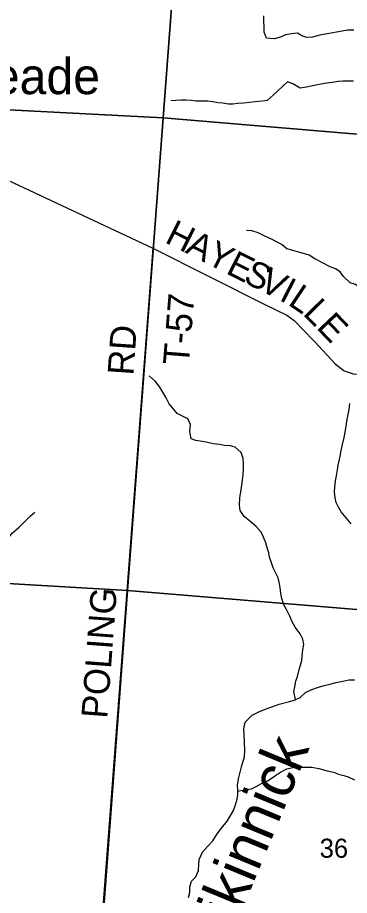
# Model space of a CAD drawing. Extents: x 0 to 42.5, y 0 to 22.
# Drawn here: x 4.623 to 4.986, y 16.014 to 16.976 of the extents above; entities that cross this region are included whole.
import ezdxf

# ---------------------------------------------------------------- set-up
doc = ezdxf.new("R2010")
doc.units = 0
for name, color, linetype in [('GM_X_County_Road', 7, 'Continuous'), ('GM_X_County_Road_Text', 7, 'Continuous'), ('GM_X_Minor_River', 7, 'Continuous'), ('GM_X_Minor_River_Text', 7, 'Continuous'), ('GM_X_Section', 7, 'Continuous'), ('GM_X_Section_Text', 7, 'Continuous'), ('GM_X_Township_Road', 7, 'Continuous'), ('GM_X_Township_Road_Text', 7, 'Continuous'), ('GM_X_Unincorporated_Text', 7, 'Continuous')]:
    doc.layers.add(name, color=color, linetype=linetype)

msp = doc.modelspace()

# ---------------------------------------------------------------- linework, layer by layer
at = {"layer": 'GM_X_County_Road'}
for points in [[(4.39163, 16.96049), (4.41637, 16.94481), (4.50621, 16.88786), (4.51318, 16.88268), (4.52161, 16.86914), (4.54011, 16.83463), (4.58198, 16.81209), (4.77079, 16.72352), (4.89442, 16.66131), (4.91761, 16.6499), (4.9257, 16.64432), (4.94699, 16.62222)], [(4.94699, 16.62222), (4.94734, 16.62187), (4.94838, 16.62078), (4.97069, 16.59667), (4.98046, 16.58918), (4.99047, 16.58587), (5.03773, 16.58279)]]:
    msp.add_lwpolyline(points, dxfattribs=at)
at = {"layer": 'GM_X_Minor_River'}
for points in [[(4.991, 16.96236), (4.98412, 16.9626), (4.97818, 16.9615), (4.97225, 16.96021), (4.96422, 16.95894), (4.95388, 16.95693), (4.94566, 16.9549), (4.93953, 16.95437), (4.93399, 16.95612), (4.92922, 16.95901), (4.9229, 16.95848), (4.9164, 16.95739), (4.91085, 16.95496), (4.90377, 16.95312), (4.89554, 16.95355), (4.89269, 16.96022), (4.8927, 16.96611), (4.89233, 16.97257), (4.89253, 16.97808)], [(4.99088, 16.9067), (4.98572, 16.90674), (4.97902, 16.9066), (4.97386, 16.90607), (4.96735, 16.90517), (4.95893, 16.9039), (4.94745, 16.90189), (4.93923, 16.90005), (4.93234, 16.89877), (4.92412, 16.90358), (4.91858, 16.90571), (4.90287, 16.8912), (4.89597, 16.88536), (4.89061, 16.88483), (4.88315, 16.88394), (4.87684, 16.88322), (4.87014, 16.88232), (4.86402, 16.88198), (4.85866, 16.88145), (4.85388, 16.8813), (4.84757, 16.88229), (4.8426, 16.8829), (4.8361, 16.88409), (4.83113, 16.8845), (4.82424, 16.88455), (4.81812, 16.88479), (4.81334, 16.8852), (4.80722, 16.88563), (4.80206, 16.88585), (4.79613, 16.88552), (4.79096, 16.88518)], [(4.87366, 16.74325), (4.87883, 16.74284), (4.8859, 16.74051), (4.89163, 16.73781), (4.90195, 16.73317), (4.90672, 16.73029), (4.91246, 16.7274), (4.91811, 16.72275)], [(5.00965, 16.61254), (5.02155, 16.63197), (5.02497, 16.63726), (5.02897, 16.64389), (5.02955, 16.64863), (5.02729, 16.65585), (5.02427, 16.66061), (5.02011, 16.66557), (5.01083, 16.6715), (5.00572, 16.67418), (4.99834, 16.67953), (4.99303, 16.68373), (4.98716, 16.68566), (4.97978, 16.69234), (4.976, 16.69748), (4.97089, 16.70092), (4.96502, 16.70323), (4.94835, 16.71166), (4.9421, 16.71568), (4.91811, 16.72275)], [(4.92712, 16.22869), (4.92542, 16.23766), (4.92638, 16.24259), (4.92772, 16.24885), (4.92944, 16.25396), (4.93135, 16.26155), (4.93269, 16.26628), (4.93403, 16.2714), (4.93461, 16.27633), (4.93539, 16.28335), (4.93616, 16.28923), (4.93522, 16.29493), (4.93239, 16.30064), (4.92691, 16.30807), (4.92332, 16.31454), (4.92087, 16.32005), (4.91728, 16.32728), (4.91445, 16.33261), (4.91219, 16.33964), (4.91126, 16.34496), (4.91051, 16.35142), (4.90939, 16.3575), (4.90808, 16.36225), (4.90562, 16.36739), (4.9026, 16.3731), (4.90091, 16.37842), (4.89884, 16.38469), (4.8979, 16.38944), (4.89621, 16.39514), (4.89451, 16.40047), (4.89225, 16.40674), (4.88961, 16.41207), (4.88412, 16.41855), (4.87731, 16.42409), (4.87107, 16.42943), (4.86653, 16.43591), (4.86578, 16.44198), (4.86618, 16.44976), (4.86715, 16.4564), (4.86811, 16.46114), (4.86907, 16.4693), (4.86985, 16.47518), (4.87005, 16.48201), (4.87006, 16.48694), (4.86989, 16.49302), (4.86763, 16.49948), (4.861, 16.5054), (4.85608, 16.50694), (4.84887, 16.50717), (4.84413, 16.50814), (4.83693, 16.50893), (4.82916, 16.51087), (4.8229, 16.51185), (4.81798, 16.51282), (4.81305, 16.51436), (4.81136, 16.52253), (4.81233, 16.53031), (4.80931, 16.53659), (4.80268, 16.53966), (4.79756, 16.54234), (4.79265, 16.54806), (4.78868, 16.55301), (4.78566, 16.55948), (4.78188, 16.56557), (4.77848, 16.57128), (4.77337, 16.57757), (4.76694, 16.58349)], [(4.98805, 16.42127), (4.98257, 16.42775), (4.97727, 16.4346), (4.97425, 16.43955), (4.9718, 16.44488), (4.97048, 16.44982), (4.96993, 16.45647), (4.97013, 16.4614), (4.9711, 16.46861), (4.97206, 16.47411), (4.97302, 16.48037), (4.97379, 16.48549), (4.97494, 16.49042), (4.97609, 16.49553), (4.97724, 16.5016), (4.97859, 16.50843), (4.98031, 16.51582), (4.98204, 16.52379), (4.98319, 16.53099), (4.98396, 16.53592), (4.98492, 16.54123), (4.98607, 16.54673), (4.98685, 16.55318)], [(4.57966, 16.36019), (4.59593, 16.36017), (4.602, 16.36356), (4.60732, 16.36809), (4.60828, 16.37378), (4.60887, 16.38118), (4.60926, 16.3863), (4.61004, 16.3937), (4.61138, 16.39996), (4.61329, 16.40621), (4.61729, 16.4115), (4.62432, 16.41754), (4.63021, 16.4234), (4.63648, 16.42982), (4.6418, 16.43416)], [(4.80996, 16.01161), (4.8113, 16.0173), (4.81151, 16.02356), (4.81323, 16.02962), (4.81817, 16.03434), (4.82103, 16.04135), (4.82142, 16.04799), (4.82182, 16.05331), (4.82544, 16.06126), (4.83133, 16.06787), (4.83666, 16.07373), (4.84142, 16.08149), (4.84598, 16.08792), (4.85226, 16.09548), (4.85568, 16.10097), (4.8593, 16.10702), (4.86121, 16.11233), (4.86312, 16.11953), (4.86408, 16.12427), (4.8641, 16.12978), (4.86354, 16.1349), (4.86469, 16.14192), (4.86622, 16.14761), (4.86795, 16.15481), (4.86986, 16.16107), (4.8712, 16.16599), (4.8716, 16.1732), (4.87143, 16.18117), (4.87107, 16.19029), (4.8707, 16.19655), (4.87205, 16.20395), (4.87965, 16.2115), (4.88706, 16.21526), (4.89503, 16.21864), (4.90129, 16.2207), (4.90926, 16.2235), (4.92046, 16.22668), (4.92596, 16.22817), (4.93223, 16.23098), (4.93812, 16.23627), (4.94514, 16.23965), (4.95255, 16.24246), (4.95843, 16.24414), (4.96469, 16.24563), (4.97171, 16.24749), (4.97911, 16.24898), (4.98575, 16.25027), (4.99182, 16.25043)], [(4.86409, 16.12826), (4.86561, 16.12882), (4.87339, 16.13011), (4.87908, 16.13103), (4.88402, 16.13328), (4.89009, 16.13686), (4.89712, 16.13986), (4.90415, 16.14476), (4.91079, 16.14929), (4.91782, 16.15286), (4.92427, 16.15435), (4.93129, 16.15469), (4.9383, 16.15447), (4.94494, 16.15443), (4.95271, 16.15326), (4.962, 16.15074), (4.96863, 16.149), (4.97432, 16.14689), (4.98, 16.14534), (4.98474, 16.14399), (4.99175, 16.14054)]]:
    msp.add_lwpolyline(points, dxfattribs=at)
at = {"layer": 'GM_X_Section'}
for points in [[(4.30758, 17.4121), (4.82097, 17.37842), (4.78227, 16.8664), (4.27419, 16.89254)], [(5.33145, 17.33215), (5.32925, 17.29977), (5.29429, 16.82733), (5.29389, 16.82335), (4.78227, 16.8664), (4.82097, 17.37842)], [(4.27419, 16.89254), (4.78227, 16.8664), (4.74326, 16.34822), (4.23674, 16.37779)], [(4.78227, 16.8664), (5.29389, 16.82335), (5.25394, 16.30596), (4.74326, 16.34822)], [(4.23674, 16.37779), (4.74326, 16.34822), (4.70496, 15.83569), (4.19513, 15.87098)], [(5.25394, 16.30596), (5.25259, 16.29706), (5.21739, 15.80037), (4.70496, 15.83569), (4.74326, 16.34822)]]:
    msp.add_lwpolyline(points, close=True, dxfattribs=at)
at = {"layer": 'GM_X_Township_Road'}
msp.add_line((4.77079, 16.72352), (4.70337, 15.83438), dxfattribs=at)

# ---------------------------------------------------------------- texts
at = {"layer": 'GM_X_County_Road_Text'}
for s, rotation, p in [('H', 333.22969, (4.78289, 16.73024)), ('A', 333.22806, (4.80521, 16.71898)), ('Y', 333.22806, (4.82753, 16.70772)), ('E', 333.22796, (4.84985, 16.69645)), ('S', 333.23147, (4.86882, 16.68688)), ('V', 333.19384, (4.88593, 16.67825)), ('I', 332.72974, (4.90819, 16.66701)), ('L', 326.13046, (4.91781, 16.6621)), ('L', 314.52574, (4.93429, 16.65123)), ('E', 313.6544, (4.94911, 16.63616))]:
    msp.add_text(s, height=0.02841, rotation=rotation, dxfattribs=at).set_placement(p)
at = {"layer": 'GM_X_Minor_River_Text'}
msp.add_text('Kinnikinnick', height=0.0473486, rotation=67.45135, dxfattribs=at).set_placement((4.81461, 15.86723))
at = {"layer": 'GM_X_Section_Text'}
msp.add_text('36', height=0.020928, rotation=0.00001, dxfattribs=at).set_placement((4.9537, 16.05528))
at = {"layer": 'GM_X_Township_Road_Text'}
for s, rotation, p in [('T-57', 85.41186, (4.81029, 16.59468)), ('RD', 86.05318, (4.74964, 16.58352)), ('POLING', 85.687, (4.72088, 16.20734))]:
    msp.add_text(s, height=0.028409, rotation=rotation, dxfattribs=at).set_placement(p)
at = {"layer": 'GM_X_Unincorporated_Text'}
msp.add_text('Meade', height=0.039489, rotation=0.00001, dxfattribs=at).set_placement((4.55162, 16.89231))

doc.saveas('drawing.dxf')
